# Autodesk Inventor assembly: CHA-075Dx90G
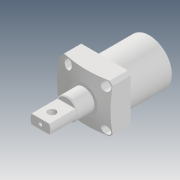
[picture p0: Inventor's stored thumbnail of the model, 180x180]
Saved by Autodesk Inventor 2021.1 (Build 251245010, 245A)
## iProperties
Created: 2019-12
Part Number: CHA-075Dx90G
Description: STEP AP203
Document SubType Name: Assembly
Designer: user
Title: CHA-075Dx90G.STEP
Revision Number: ÈÎºÎ
Sending System: SolidWorks 2017
Preprocessor: SwSTEP 2.0
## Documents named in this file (4)
- D:\Vault_2016\Projekty\Clamptek\Hydraulic\CHA\CHA\CHA-075\Inventor\CHA-075Dx90G\CHA-075Dx90G.iam
- D:\Vault_2016\Projekty\Clamptek\Hydraulic\CHA\CHA\CHA-075\Inventor\CHA-075Dx90G\CHA-075±¾Ìå.ipt
- D:\Vault_2016\Projekty\Clamptek\Hydraulic\CHA\CHA\CHA-075\Inventor\CHA-075Dx90G\G1-4¶ÂÍ·_1.ipt
- D:\Vault_2016\Projekty\Clamptek\Hydraulic\CHA\CHA\CHA-075\Inventor\CHA-075Dx90G\CHA-075D(Ë«±Û£©»îÈû¸Ë_1.ipt
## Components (4 placed, 4 different names)
1. CHA-075±¾Ìå_1
2. G1-4¶ÂÍ·_1_2
3. CHA-075D(Ë«±Û£©»îÈû¸Ë_1_3
4. G1-4¶ÂÍ·_1_4
